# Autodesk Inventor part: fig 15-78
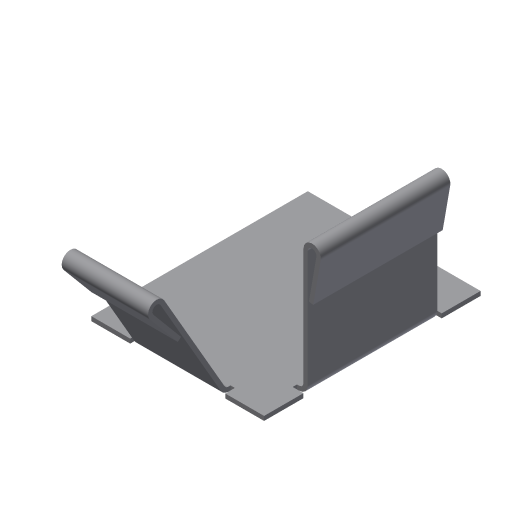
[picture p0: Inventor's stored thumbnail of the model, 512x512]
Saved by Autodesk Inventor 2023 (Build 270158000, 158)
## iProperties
Created: 2002-04
Part Number: fig 15-78
Document SubType Name: Sheet Metal
Density: 1 g/cm^3
Sheet Metal Rule: Default
Material: Generic
Appearance: Default
Control State: 0
Master: False
Checked Out: False
Shininess: 77.0
Angle Display Precision: 2
Document Length Units: 11269
Document Angle Units: 11279
Document Time Units: 11290
Document Mass Units: 11283
Document Length Units Precision: 3
Document Angle Units Precision: 2
Compacted: True
Density: 0.0
Volumn: 0.0
Area: 0.0
PropertySet Name: Model Information
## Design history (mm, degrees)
node "Face1"
  sketch "Sketch1"
    geometry: L1 (-17.882, 11.882)-(2.118, 11.882); L2 (2.118, 11.882)-(2.118, -13.176); L3 (2.118, -13.176)-(-17.882, -13.176); L4 (-17.882, -13.176)-(-17.882, 11.882)
    constraints: 8 end point, 2 parallel, 1 horizontal, 1 perpendicular
    dimensions: "d17" = 20 distance of L2.end L3.end
node "Flange2"
node "Flange3"
feature "Hem8" dims "d82" = 0.5 (= BendReliefWidth), "d83" = 0.25 (= BendReliefDepth), "d84" = 1 (= MinimumRemnant), "d85" = 0.5 (= BendRadius), "d96" = 190 deg, "d97" = 0.5 (= BendRadius), "d98" = 0.5 (= d97), "d102" = 0.5 (= Thickness), "SeamGap" = 0.01
feature "Hem9" dims "d89" = 0.5 (= BendReliefWidth), "d90" = 0.25 (= BendReliefDepth), "d91" = 1 (= MinimumRemnant), "d92" = 0.5 (= BendRadius), "d99" = 190 deg, "d100" = 0.5 (= BendRadius), "d101" = 0.5 (= d100), "d102" = 0.5 (= Thickness), "SeamGap" = 0.01
body "Solid1"
face "Plate1" dims "d102" = 0.5 (= Thickness)
sketch "Sketch3"
  geometry: L1 (5, 0)-(20, 0); L2 (20, 0)-(20, 15); L3 (20, 15)-(5, 15); L4 (5, 15)-(5, 0)
  constraints: 8 end point
face "Plate3" dims "d6" = 15, "d7" = 90 deg, "d8" = 0.5 (= BendRadius), "d18" = 5, "d19" = 15, "d102" = 0.5 (= Thickness), "MinimumRemnant" = 1 (= 2 x Thickness), "BendReliefWidth" = 0.5 (= Thickness)
bend "Bend2" dims "d6" = 15, "d7" = 90 deg, "d8" = 0.5 (= BendRadius), "d56" = 0.5 (= BendReliefWidth), "d57" = 0.25 (= BendReliefDepth), "d58" = 1 (= MinimumRemnant), "d102" = 0.5 (= Thickness), "SeamGap" = 0.01, "MinimumRemnant" = 1 (= 2 x Thickness), "BendReliefWidth" = 0.5 (= Thickness), "TransitionRadius" = 0.5 (= BendRadius)
sketch "Sketch6"
  geometry: L1 (15, 0)-(5, 0); L2 (5, 0)-(5, 15); L3 (5, 15)-(15, 15); L4 (15, 15)-(15, 0)
  constraints: 8 end point
face "Plate4" dims "d20" = 5, "d21" = 10, "d23" = 15, "d24" = 60 deg, "d25" = 0.5 (= BendRadius), "d102" = 0.5 (= Thickness), "MinimumRemnant" = 1 (= 2 x Thickness), "BendReliefWidth" = 0.5 (= Thickness)
bend "Bend3" dims "d22" = 0.5 (= BendRadius), "d23" = 15, "d24" = 60 deg, "d25" = 0.5 (= BendRadius), "d59" = 0.5 (= BendReliefWidth), "d60" = 0.25 (= BendReliefDepth), "d61" = 1 (= MinimumRemnant), "d102" = 0.5 (= Thickness), "SeamGap" = 0.01, "MinimumRemnant" = 1 (= 2 x Thickness), "BendReliefWidth" = 0.5 (= Thickness)
sketch "Sketch12"
  geometry: L1 (0.433, 0.25)-(0, 0); L2 (-0.816, -0.571)-(2.395, -4.398); L3 (2.395, -4.398)-(2.012, -4.719); L4 (2.012, -4.719)-(-1.199, -0.893); A1 r 0.5 centre (-0.433, -0.25) between (0, 0) and (-0.816, -0.571); A2 r 1 centre (-0.433, -0.25) between (0.433, 0.25) and (-1.199, -0.893); 2 further points
  constraints: 8 end point, 4 point on circle
sketch "Sketch13"
  geometry: L1 (0.5, 0)-(0, 0); L2 (-0.992, -0.087)-(-0.125, -5.006); L3 (-0.125, -5.006)-(-0.617, -5.093); L4 (-0.617, -5.093)-(-1.485, -0.174); A1 r 0.5 centre (-0.5, 0) between (0, 0) and (-0.992, -0.087); A2 r 1 centre (-0.5, 0) between (0.5, 0) and (-1.485, -0.174); 2 further points
  constraints: 8 end point, 4 point on circle
other parameters: "Thickness" = 0.5, "BendRadius" = 0.5 (= Thickness), "BendReliefDepth" = 0.25 (= 0.5 x Thickness), "CornerReliefSize" = 2 (= 4 x Thickness), "d0" = 0.5 (= BendRadius), "d5" = 0.5 (= BendRadius), "d26" = 0.5 (= BendRadius), "d30" = 0.5 (= BendRadius), "JacobiRadiusSize" = 0.5 (= Thickness), "GapSize" = 0.5 (= Thickness)
